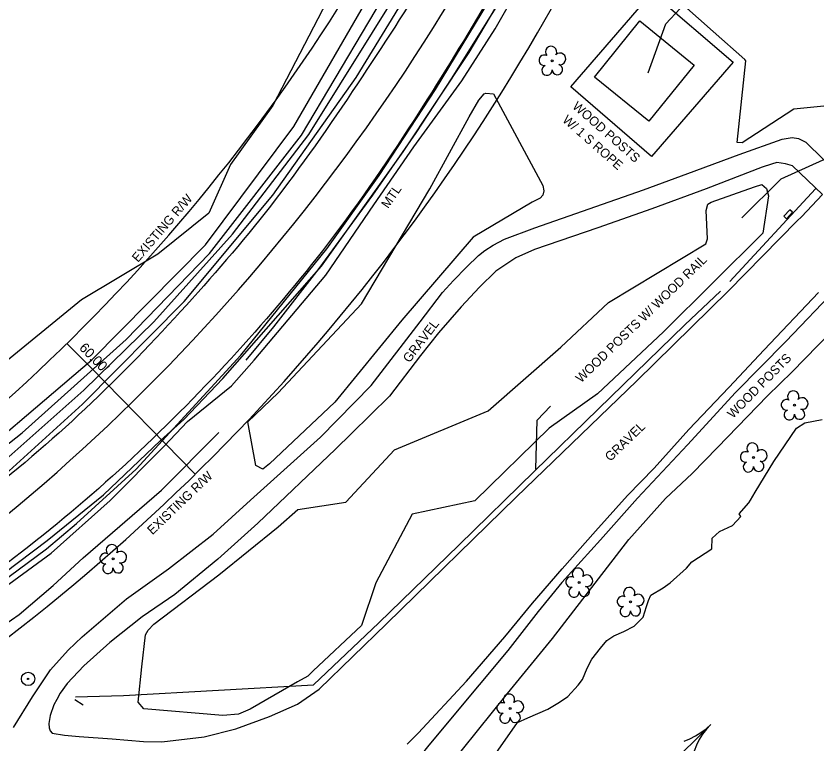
# Model space of a CAD drawing. Extents: x 1645945 to 2447332, y 713118 to 970361.
# Drawn here: x 1647554 to 1647816.3, y 969653 to 969891.3 of the extents above; entities that cross this region are included whole.
import ezdxf

# ---------------------------------------------------------------- set-up
doc = ezdxf.new("R2010")
doc.units = 0
for name, color, linetype in [('Exist Guardrail', 7, 'Continuous'), ('Exist Guardrail Text', 7, 'Continuous'), ('Exist Horizontal Alignment', 7, 'Continuous'), ('Exist Hydro Jurisdictional Stream or Body of Water', 7, 'Continuous'), ('Exist Hydro River Flow Arrow CELL', 7, 'Continuous'), ('Exist Other Culture Area Outline', 7, 'Continuous'), ('Exist Other Culture Fence Line', 7, 'Continuous'), ('Exist Other Culture Fence Line Leader', 7, 'Continuous'), ('Exist Other Culture Fence Line Text', 7, 'Continuous'), ('Exist Other Culture Located Object CELL', 7, 'Continuous'), ('Exist Other Culture Sign CELL', 7, 'Continuous'), ('Exist Right of Way Line', 7, 'Continuous'), ('Exist Right of Way Line Text', 7, 'Continuous'), ('Exist Right of Way Width CELL', 7, 'Continuous'), ('Exist Roads EOP', 7, 'Continuous'), ('Exist Roads Soil', 7, 'Continuous'), ('Exist Roads Soil Text', 7, 'Continuous'), ('Exist Utilities Sanitary Sewer Forced Main SUE LOS B', 7, 'Continuous'), ('Exist Utilities Sanitary Sewer Forced Main SUE LOS C', 7, 'Continuous'), ('Exist Utilities Telephone UG Cable SUE LOS C', 7, 'Continuous'), ('Exist Utilities Telephone UG Conduit SUE LOS B', 7, 'Continuous'), ('Exist Utilities Telephone UG FO SUE LOS C', 7, 'Continuous'), ('Exist Vegetation Tree CELL', 7, 'Continuous'), ('Exist Vegetation Woods Line', 7, 'Continuous')]:
    doc.layers.add(name, color=color, linetype=linetype)

msp = doc.modelspace()

# ---------------------------------------------------------------- linework, layer by layer
at = {"layer": 'Exist Guardrail'}
msp.add_lwpolyline([(1647760.77, 969982.88), (1647754.03, 969970.46), (1647741.47, 969946.85), (1647730.08, 969925.76), (1647717.26, 969903.89), (1647707.96, 969889.08), (1647696.73, 969871.06), (1647684.96, 969853.08), (1647670.81, 969832.67), (1647653.24, 969808.63), (1647638.37, 969789.54), (1647629.29, 969778.66)], dxfattribs=at)
at = {"layer": 'Exist Horizontal Alignment'}
msp.add_arc((1647126.83, 970240.1), 665, 298.87121, 329.93673, dxfattribs=at)
at = {"layer": 'Exist Hydro Jurisdictional Stream or Body of Water'}
msp.add_lwpolyline([(1647707.3, 969644.42), (1647718.24, 969660.04), (1647721.66, 969661.59), (1647728.17, 969664.4), (1647731.98, 969666.76), (1647734.76, 969668.6), (1647738.11, 969672.23), (1647739.51, 969674.16), (1647741.12, 969677.86), (1647742.63, 969680.73), (1647745.45, 969684.36), (1647747.5, 969686.93), (1647749.85, 969688.42), (1647753.12, 969689.8), (1647756.47, 969691.63), (1647759.41, 969694.56), (1647760.56, 969698.02), (1647761.11, 969700), (1647761.9, 969701.73), (1647766.01, 969704.11), (1647768.26, 969705.75), (1647773.56, 969710.55), (1647775.4, 969712.61), (1647781.95, 969716.87), (1647781.98, 969720.4), (1647784.41, 969722.56), (1647788.69, 969724.58), (1647791.39, 969727.47), (1647790.9, 969728.33), (1647794.03, 969731.99), (1647794.57, 969732.83), (1647796.1, 969735.45), (1647802.19, 969745.51), (1647809.68, 969756.43), (1647812.33, 969758.15), (1647818.01, 969759.19)], dxfattribs=at)
at = {"layer": 'Exist Hydro River Flow Arrow CELL'}
msp.add_lwpolyline([(1647772.83, 969653.96), (1647774.73, 969654.73), (1647776.58, 969655.68), (1647778.35, 969656.78), (1647780.03, 969658), (1647781.53, 969659.4), (1647767.37, 969645.27), (1647781.53, 969659.4), (1647780.13, 969657.9), (1647778.9, 969656.23), (1647777.79, 969654.45), (1647776.85, 969652.61), (1647776.07, 969650.72)], dxfattribs=at)
at = {"layer": 'Exist Other Culture Area Outline'}
for points in [[(1647758.3, 969889.69), (1647776.16, 969875.22), (1647761.31, 969856.88), (1647743.44, 969871.34)], [(1647805.47, 969825.75), (1647806.32, 969824.94), (1647808.34, 969827.05), (1647807.49, 969827.86)]]:
    msp.add_lwpolyline(points, close=True, dxfattribs=at)
at = {"layer": 'Exist Other Culture Fence Line'}
msp.add_line((1647787.84, 969804.39), (1647815.88, 969834.71), dxfattribs=at)
msp.add_lwpolyline([(1647788.87, 969876.21), (1647762.15, 969845.28), (1647735.67, 969868.17), (1647762.41, 969899.05)], close=True, dxfattribs=at)
for points in [[(1647836.14, 969816.64), (1647822.8, 969802.2), (1647806.1, 969784.74), (1647789.66, 969768.09), (1647773.88, 969750.97), (1647757.53, 969733.44), (1647745.42, 969719.82), (1647732.73, 969705.92), (1647724.99, 969696.36), (1647715.08, 969683.63), (1647696.29, 969661.16), (1647688.81, 969652.14), (1647674.62, 969634.09), (1647646.6, 969611.84)], [(1647651.93, 969606.23), (1647662.05, 969613.58), (1647671.87, 969620.9), (1647679.68, 969627.22), (1647689.25, 969637.47), (1647700.19, 969651.24), (1647715.02, 969669.5), (1647729.67, 969687.53), (1647754.77, 969719.94), (1647766.77, 969733.37), (1647775.43, 969741.53), (1647783.81, 969750.03), (1647800.17, 969766.99), (1647808.26, 969774.85), (1647820.92, 969787.78), (1647846.68, 969812.64)], [(1647573.53, 969668.42), (1647589.2, 969668.86), (1647651.46, 969672.33), (1647672.87, 969692.68), (1647699.03, 969718.12), (1647723.82, 969742.35), (1647744.71, 969762.59), (1647773.06, 969790.25), (1647784.72, 969801.22)], [(1647378.48, 969599.04), (1647397.5, 969607.19), (1647419.7, 969617.12), (1647432.85, 969623.77), (1647446.7, 969631.34), (1647460.79, 969639.34), (1647468.57, 969643.81), (1647481.65, 969651.11), (1647495.44, 969658.93), (1647516.04, 969670.64), (1647542.37, 969686.67), (1647555.03, 969695.43), (1647566.23, 969704.89), (1647576.04, 969713.96), (1647601.68, 969736.14), (1647620.49, 969754.94)]]:
    msp.add_lwpolyline(points, dxfattribs=at)
at = {"layer": 'Exist Other Culture Fence Line Leader'}
for points in [[(1647761.01, 969872.67), (1647766.89, 969888.75), (1647776.2, 969898.94)], [(1647827.43, 969848.22), (1647804.53, 969837.88), (1647791.71, 969825.2)], [(1647724.3, 969743.01), (1647724.74, 969759.03), (1647729.09, 969763.6)]]:
    msp.add_lwpolyline(points, dxfattribs=at)
at = {"layer": 'Exist Other Culture Located Object CELL'}
for radius in [2.18, 0.24]:
    msp.add_circle((1647557.98, 969674.32), radius, dxfattribs=at)
at = {"layer": 'Exist Other Culture Sign CELL'}
msp.add_line((1647573.32, 969667.57), (1647575.97, 969665.8), dxfattribs=at)
at = {"layer": 'Exist Right of Way Line'}
msp.add_line((1647724.81, 969885.85), (1647750.92, 969930.96), dxfattribs=at)
for radius in [620, 680]:
    msp.add_arc((1647136.28, 970226.5), radius, 299.46236, 329.93673, dxfattribs=at)
at = {"layer": 'Exist Right of Way Width CELL'}
for p in [(1647570.7, 969784.14), (1647612.74, 969741.33)]:
    msp.add_line(p, (1647578.48, 969776.22), dxfattribs=at)
at = {"layer": 'Exist Roads EOP'}
for points in [[(1647712.71, 969946.05), (1647689.83, 969906.56), (1647665.85, 969869.13), (1647637.34, 969829.12), (1647607.92, 969794.57), (1647574.53, 969760.72), (1647538.69, 969730.5), (1647499.85, 969702.79), (1647457.34, 969676.33), (1647411.66, 969651.37), (1647366.8, 969630.41), (1647321.37, 969611.83), (1647279.28, 969597.97), (1647224.82, 969583.15), (1647179.92, 969574.15), (1647132.17, 969565.53), (1647083.22, 969557.97), (1647036.22, 969550.58), (1646989.26, 969543.73)], [(1647731.3, 969935.45), (1647707.71, 969895.07), (1647684.27, 969857.13), (1647654.38, 969814.5), (1647624.46, 969779.25), (1647589.97, 969744.66), (1647553.5, 969714.01), (1647512.43, 969684.95), (1647469.3, 969658.19), (1647421.26, 969632.07), (1647375.68, 969609.9), (1647329.15, 969590.49), (1647286.02, 969576.26), (1647230.19, 969561.18), (1647183.04, 969552.75), (1647135.89, 969544.58), (1647086.4, 969536.99), (1647040.14, 969529.53), (1646992.05, 969522.32)]]:
    msp.add_spline(points, degree=3, dxfattribs=at)
at = {"layer": 'Exist Roads Soil'}
for points in [[(1647553.18, 969658.4), (1647559.42, 969668.42), (1647565.26, 969677.25), (1647571.06, 969683.73), (1647575.73, 969688.14), (1647590.21, 969700.55), (1647603.9, 969710.34), (1647618.58, 969721.68), (1647630.78, 969732.81), (1647653.76, 969753.44), (1647670.34, 969770.37), (1647686.38, 969791.26), (1647693.71, 969800.83), (1647697.3, 969804.73), (1647701.52, 969809.14), (1647705.43, 969812.97), (1647707.51, 969814.6), (1647710.34, 969816.35), (1647713.98, 969818.23), (1647723.93, 969822), (1647759.52, 969834.45), (1647774.06, 969839.71), (1647790.87, 969845.98), (1647804.98, 969851.01), (1647808.22, 969851.55), (1647810.34, 969851.17), (1647812.7, 969850), (1647823.96, 969838.96)], [(1647682.1, 969652.91), (1647685.72, 969656.58), (1647701.51, 969673.6), (1647714.09, 969688.14), (1647723.17, 969699.14), (1647732.9, 969710.39), (1647743.78, 969722.68), (1647754.26, 969734.32), (1647762.97, 969743.26), (1647774.42, 969755.95), (1647787.45, 969769.72), (1647799, 969781.99), (1647816.85, 969800.78)]]:
    msp.add_lwpolyline(points, dxfattribs=at)
msp.add_lwpolyline([(1647658.69, 969749.56), (1647633.16, 969725.35), (1647620.06, 969713.57), (1647606.02, 969701.93), (1647595.32, 969694.61), (1647584.7, 969686.28), (1647576.23, 969678.6), (1647570.79, 969672.8), (1647568.44, 969669.61), (1647567.33, 969667.61), (1647566.37, 969665.78), (1647565.18, 969662.35), (1647564.79, 969659.71), (1647564.86, 969658.27), (1647565.21, 969657.35), (1647565.86, 969656.54), (1647569.88, 969655.94), (1647574.7, 969655.5), (1647585.53, 969654.67), (1647595.74, 969653.84), (1647601.81, 969653.71), (1647615.59, 969655.39), (1647626, 969657.95), (1647637, 969661.98), (1647646.22, 969666.01), (1647653.27, 969670.97), (1647675.4, 969692.36), (1647717.82, 969733.84), (1647757.34, 969771.91), (1647787.24, 969801.24), (1647809.89, 969824.29), (1647811.28, 969825.55), (1647818.19, 969832.9), (1647808.35, 969842.22), (1647806.05, 969842.98), (1647803.18, 969843.35), (1647801.49, 969842.85), (1647798.35, 969841.87), (1647780.04, 969834.74), (1647762.27, 969828.16), (1647744.58, 969822.02), (1647723.81, 969814.89), (1647717.75, 969812.21), (1647711.15, 969807.74), (1647705.76, 969802.51), (1647699.77, 969796.09), (1647692.42, 969787.65), (1647686.53, 969780.19), (1647676.3, 969766.86), (1647663.94, 969754.63)], close=True, dxfattribs=at)
at = {"layer": 'Exist Utilities Sanitary Sewer Forced Main SUE LOS B'}
msp.add_lwpolyline([(1647281.82, 969570.96), (1647301.43, 969576.57), (1647317.63, 969582.51), (1647339.14, 969590.95), (1647371.77, 969606.21), (1647423.35, 969630.3), (1647468.23, 969654.45), (1647489.07, 969666.65), (1647526.6, 969691.29), (1647564.25, 969719.63), (1647582.69, 969734.56), (1647601.35, 969752.36), (1647608.99, 969759.23), (1647621.71, 969772.62)], dxfattribs=at)
at = {"layer": 'Exist Utilities Sanitary Sewer Forced Main SUE LOS C'}
msp.add_lwpolyline([(1647621.71, 969772.62), (1647654.05, 969809.43), (1647680.79, 969846.9), (1647702.42, 969879.41), (1647734.22, 969933.03), (1647790.69, 970040.12), (1647806.93, 970074.53)], dxfattribs=at)
at = {"layer": 'Exist Utilities Telephone UG Cable SUE LOS C'}
for points in [[(1647301.18, 969607.49), (1647346.35, 969625.33), (1647402.72, 969651.12), (1647431.08, 969666.24), (1647439.41, 969670.62), (1647442.16, 969672.78), (1647445.5, 969676.48), (1647448.63, 969678.56), (1647474.06, 969693.41), (1647520.52, 969726.92), (1647556, 969754.87), (1647590.11, 969785.42), (1647617.35, 969813.54), (1647647.46, 969852.3), (1647702.67, 969945.18), (1647775.84, 970087.47)], [(1647299.74, 969604.87), (1647344.43, 969621.93), (1647402.05, 969647.91), (1647428.7, 969661.61), (1647441.47, 969668.79), (1647444.57, 969671.27), (1647446.47, 969673.44), (1647447.93, 969674.84), (1647451.1, 969676.98), (1647475.41, 969691.19), (1647501.84, 969708.82), (1647529.96, 969729.71), (1647548.6, 969744.41), (1647576.21, 969768.81), (1647599.16, 969791.2), (1647624.94, 969819.94), (1647649.96, 969852.56), (1647680.88, 969902.23), (1647705.82, 969944.72), (1647779.36, 970085.84)], [(1647294.11, 969544.68), (1647330.92, 969585.92), (1647342.26, 969590.26), (1647406.15, 969619.43), (1647450.3, 969642.78), (1647488.96, 969665.16), (1647521.25, 969685.99), (1647545.76, 969703.5), (1647563.98, 969716.93), (1647573.87, 969725.16), (1647593.32, 969742.95), (1647627.6, 969780.32), (1647655.82, 969815.07), (1647672.99, 969839.14), (1647691.44, 969867.28), (1647722.34, 969918.27), (1647755.1, 969977.16), (1647804.4, 970074.3)]]:
    msp.add_lwpolyline(points, dxfattribs=at)
at = {"layer": 'Exist Utilities Telephone UG Conduit SUE LOS B'}
msp.add_lwpolyline([(1647528.7, 969688.64), (1647565.5, 969715.45), (1647584.81, 969732.68), (1647602.51, 969750.52), (1647610.22, 969758.56), (1647624.57, 969770.24), (1647632, 969778.64), (1647655.51, 969806.51), (1647671.15, 969829.51), (1647684.31, 969848.46), (1647700.06, 969870.14), (1647710.99, 969887.15), (1647722.81, 969908.11), (1647733.12, 969926.03), (1647751.45, 969960.54), (1647769.23, 969993.85), (1647778.74, 970010.99), (1647787.31, 970029.01), (1647808.48, 970072.42)], dxfattribs=at)
at = {"layer": 'Exist Utilities Telephone UG FO SUE LOS C'}
for points in [[(1647289.7, 969609.34), (1647343.59, 969629.58), (1647397.62, 969653.63), (1647450.96, 969681.88), (1647471.14, 969694.21), (1647529.28, 969736.65), (1647578.89, 969778.78), (1647616.07, 969816.36), (1647645.02, 969855.2), (1647696.33, 969943.83), (1647771.33, 970089.55)], [(1647291.19, 969605.96), (1647345.09, 969627.35), (1647401.66, 969653.17), (1647434.03, 969670.53), (1647438.26, 969672.06), (1647445.18, 969672.38), (1647450.09, 969673.09), (1647455.34, 969675.46), (1647473.43, 969686.09), (1647508.86, 969709.29), (1647532.76, 969727.04), (1647549.35, 969740.28), (1647575.78, 969764.21), (1647609.03, 969797.83), (1647638.13, 969832.64), (1647665.39, 969871.17), (1647698.7, 969925.68), (1647740.76, 970001.75), (1647782.56, 970084.37)]]:
    msp.add_lwpolyline(points, dxfattribs=at)
at = {"layer": 'Exist Vegetation Tree CELL'}
for p, q in [((1647729.63, 969876.68), (1647729.63, 969876.68)), ((1647808.96, 969763.89), (1647808.96, 969763.89)), ((1647795.58, 969746.83), (1647795.58, 969746.83)), ((1647585.79, 969713.59), (1647585.79, 969713.59)), ((1647738.44, 969705.88), (1647738.44, 969705.88)), ((1647755.25, 969699.53), (1647755.25, 969699.53)), ((1647715.84, 969664.64), (1647715.84, 969664.64))]:
    msp.add_line(p, q, dxfattribs=at)
for centre in [(1647729.63, 969876.68), (1647808.96, 969763.89), (1647795.58, 969746.83), (1647585.79, 969713.59), (1647738.44, 969705.88), (1647755.25, 969699.53), (1647715.84, 969664.64)]:
    msp.add_circle(centre, 0.326, dxfattribs=at)
for centre, radius, start, end in [((1647729.25, 969879.55), 1.86, 330.1651, 219.7134), ((1647732.18, 969877.27), 1.9, 257.1011, 134.1999), ((1647727.03, 969876.83), 1.73, 62.6636, 279.3457), ((1647727.93, 969873.56), 1.69, 111.5671, 6.231), ((1647731.31, 969873.78), 1.7, 181.2822, 74.56), ((1647808.58, 969766.76), 1.86, 330.1651, 219.7134), ((1647811.51, 969764.48), 1.9, 257.1011, 134.1999), ((1647806.36, 969764.05), 1.73, 62.6636, 279.3457), ((1647807.26, 969760.77), 1.69, 111.5671, 6.231), ((1647810.64, 969760.99), 1.7, 181.2822, 74.56), ((1647795.19, 969749.7), 1.86, 330.1651, 219.7134), ((1647792.97, 969746.98), 1.73, 62.6636, 279.3457), ((1647798.13, 969747.42), 1.9, 257.1011, 134.1999), ((1647793.88, 969743.71), 1.69, 111.5671, 6.231), ((1647797.25, 969743.93), 1.7, 181.2822, 74.56), ((1647585.41, 969716.47), 1.86, 330.1651, 219.7134), ((1647583.19, 969713.75), 1.73, 62.6636, 279.3457), ((1647588.34, 969714.18), 1.9, 257.1011, 134.1999), ((1647584.09, 969710.47), 1.69, 111.5671, 6.231), ((1647587.47, 969710.69), 1.7, 181.2822, 74.56), ((1647738.06, 969708.75), 1.86, 330.1651, 219.7134), ((1647735.84, 969706.04), 1.73, 62.6636, 279.3457), ((1647740.99, 969706.47), 1.9, 257.1011, 134.1999), ((1647736.74, 969702.76), 1.69, 111.5671, 6.231), ((1647740.12, 969702.98), 1.7, 181.2822, 74.56), ((1647754.86, 969702.4), 1.86, 330.1651, 219.7134), ((1647752.64, 969699.68), 1.73, 62.6636, 279.3457), ((1647757.8, 969700.12), 1.9, 257.1011, 134.1999), ((1647753.54, 969696.41), 1.69, 111.5671, 6.231), ((1647756.92, 969696.63), 1.7, 181.2822, 74.56), ((1647715.46, 969667.52), 1.86, 330.1651, 219.7134), ((1647713.24, 969664.8), 1.73, 62.6636, 279.3457), ((1647718.39, 969665.23), 1.9, 257.1011, 134.1999), ((1647714.14, 969661.52), 1.69, 111.5671, 6.231), ((1647717.51, 969661.74), 1.7, 181.2822, 74.56)]:
    msp.add_arc(centre, radius, start, end, dxfattribs=at)
at = {"layer": 'Exist Vegetation Woods Line'}
for points in [[(1647824.83, 970077.33), (1647839.22, 969978.28), (1647855.08, 969897.94), (1647854.31, 969895.44), (1647851.54, 969892.5), (1647824.08, 969862.82), (1647821.91, 969862.11), (1647808.81, 969860.85), (1647791.79, 969849.82), (1647790.19, 969849.9), (1647792.99, 969876.68), (1647792.7, 969877.05), (1647782.35, 969886.2), (1647760.24, 969905.93), (1647750.48, 969913.52), (1647750.47, 969913.55), (1647746.78, 969914.04), (1647739.49, 969914.41), (1647738.63, 969915.59), (1647738.2, 969917.48), (1647770.38, 969971.84), (1647786.35, 970008.59), (1647806.57, 970059.22), (1647816.29, 970081.77)], [(1647733.57, 970035.54), (1647699.58, 969970.2), (1647667.04, 969936.34), (1647660.42, 969926.24), (1647657.35, 969899.17), (1647638.11, 969862.07), (1647624.3, 969842.67), (1647617.2, 969826.74), (1647600.44, 969813.37), (1647575.42, 969798.45), (1647547.21, 969775.36)], [(1647710.38, 969865.88), (1647726.58, 969835.86), (1647726.88, 969834.12), (1647726.53, 969832.69), (1647725.65, 969831.73), (1647723.04, 969830.34), (1647703.75, 969818.93), (1647680.39, 969791.78), (1647658.48, 969764.92), (1647637.06, 969744.7), (1647634.89, 969743.03), (1647632.53, 969744.18), (1647629.93, 969758.48), (1647639.83, 969767.98), (1647667.12, 969797.11), (1647689.49, 969834.76), (1647702.4, 969858.26), (1647705.57, 969863.79), (1647707.31, 969865.84), (1647707.87, 969866.07), (1647710.38, 969865.88)]]:
    msp.add_lwpolyline(points, dxfattribs=at)
msp.add_lwpolyline([(1647599.16, 969692.24), (1647620.43, 969708.38), (1647639.89, 969724.08), (1647646.31, 969729.78), (1647662.04, 969732.22), (1647678.01, 969749.36), (1647708.63, 969762.06), (1647732.47, 969782.93), (1647748.06, 969797.52), (1647779.95, 969816.77), (1647780.51, 969818.42), (1647780.08, 969827.61), (1647780.56, 969829.68), (1647781.65, 969830.37), (1647795.9, 969835.38), (1647798.29, 969836.19), (1647799.79, 969834.81), (1647800.5, 969832.41), (1647798.66, 969820.23), (1647766.03, 969787.92), (1647744.43, 969767.66), (1647728.6, 969756.45), (1647704.26, 969732.62), (1647683.71, 969728.28), (1647671.81, 969705.79), (1647667.16, 969691.76), (1647651.3, 969676.96), (1647649.58, 969675.22), (1647646.15, 969673.33), (1647630.7, 969664.38), (1647626.86, 969662.77), (1647621.78, 969662.35), (1647595.92, 969664.55), (1647594.01, 969666.66), (1647595.17, 969678.28), (1647596.47, 969688.76), (1647597.28, 969690.3)], close=True, dxfattribs=at)

# ---------------------------------------------------------------- texts
at = {"layer": 'Exist Guardrail Text'}
msp.add_text('MTL', height=3, rotation=55.2609, dxfattribs=at).set_placement((1647675.86, 969828.12))
at = {"layer": 'Exist Other Culture Fence Line Text'}
for s, rotation, p in [('WOOD POSTS', 318.653, (1647736.01, 969861.37)), ('W/ 1 S ROPE', 318.653, (1647732.74, 969856.93)), ('WOOD POSTS W/ WOOD RAIL', 44.091, (1647739.06, 969771.06)), ('WOOD POSTS', 45.3491, (1647788.79, 969759.39))]:
    msp.add_text(s, height=3, rotation=rotation, dxfattribs=at).set_placement(p)
at = {"layer": 'Exist Right of Way Line Text'}
for rotation, p in [(49.1104, (1647593.95, 969810.49)), (43.7166, (1647598.7, 969721.32))]:
    msp.add_text('EXISTING R/W', height=3, rotation=rotation, dxfattribs=at).set_placement(p)
at = {"layer": 'Exist Right of Way Width CELL'}
msp.add_text("60.00'", height=3.2, rotation=314.4812, dxfattribs=at).set_placement((1647574.5, 969782.45))
at = {"layer": 'Exist Roads Soil Text'}
for rotation, p in [(52.4844, (1647682.83, 969777.6)), (43.9353, (1647748.63, 969745.33))]:
    msp.add_text('GRAVEL', height=3, rotation=rotation, dxfattribs=at).set_placement(p)

doc.saveas('drawing.dxf')
